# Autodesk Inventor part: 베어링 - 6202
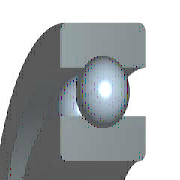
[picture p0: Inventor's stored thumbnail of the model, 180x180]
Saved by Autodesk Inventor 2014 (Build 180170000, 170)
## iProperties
IsCustomPart: 1
Created: 2015-09
Part Number: 베어링 - 6202
Material: 강, 연강
Description: 깊은 그루브 볼 베어링
Document SubType Name: Modeling
Standard: KS B 2023
Designer: mduedu
Standards Organization: KS
Language: ko-KR
Size Designation: 6202 - 15 x 35 x 11
Categories: <MemberInstance><Categories><Category DisplayName="샤프트 부품" InternalName="7f7aeb1f-a693-4053-b835-cee3144e0d98" Mnemonic="SHFT"><Category DisplayName="베어링" Inter
Density: 7.86 g/cm^3
Mass: 45.8725 g
Surface Area: 51.5584 cm^2
Volume: 5.83619 cm^3
Appearance: 크롬 - 광택
Author: mduedu
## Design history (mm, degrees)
sketch "스케치" dims "d0" = 5.2 (= -0.26 x WD + 0.26 x BD)
  geometry: L1 (2.9, 12.5)-(8.1, 12.5); L2 (5.5, 12.5)-(5.5, 9.9); L3 (5.5, 12.5)-(5.5, 15.1); L4 (3.568, 10.76)-(0, 10.76); L5 (0, 7.5)-(11, 7.5); L6 (3.568, 14.24)-(0, 14.24); L7 (0, 17.5)-(11, 17.5); L8 (11, 7.5)-(11, 10.76); L9 (7.432, 10.76)-(11, 10.76); L10 (7.432, 14.24)-(11, 14.24); L11 (11, 17.5)-(11, 14.24); L12 (-1.4, 0)-(8.4, 0) reference; L13 (0, -0.3)-(0, 5.3) reference
  constraints: 22 end point, 4 point on line, 2 collinear, 2 perpendicular, 2 symmetric about line, 1 midpoint, 1 parallel, 14 other
  dimensions: "d9" = 15 diameter of L5 L12 (= WD); "d11" = 35 diameter of L7 L12 (= BD); "d12" = 11 distance between parallel lines of L8 L13 (= KB); "d13" = 21.52 diameter of L9 L12 (= 0.326 x BD + 0.674 x WD)
revolve "본체" stored, may be unused: angle "d6" = 90 deg
revolve "볼" stored, may be unused: angle "d7" = 90 deg
pattern_circular "IDS_ARRAYBALL[SIMPL:T]" dims angle "d3" = 360 deg
body "Solid1"
fillet "모깎기1" dims "d1" = 0.6 (= KRS)
other parameters: "WD" = 15 [user parameter; used in 5 equation terms], "BD" = 35 [user parameter; used in 5 equation terms], "KB" = 11 [user parameter; used in 1 equation term], "KRS" = 0.6 [user parameter; used in 1 equation term], "d4" = 0, "d5" = 0, "d8" = 0, "d14" = 0, "d15" = 0, "BBA" = 0 [user parameter], "BC0" = 3750000 [user parameter], "BC" = 7800000 [user parameter], "BR" = 17.5 (= 0.5 x BD) [user parameter], "WR" = 7.5 (= 0.5 x WD) [user parameter]
